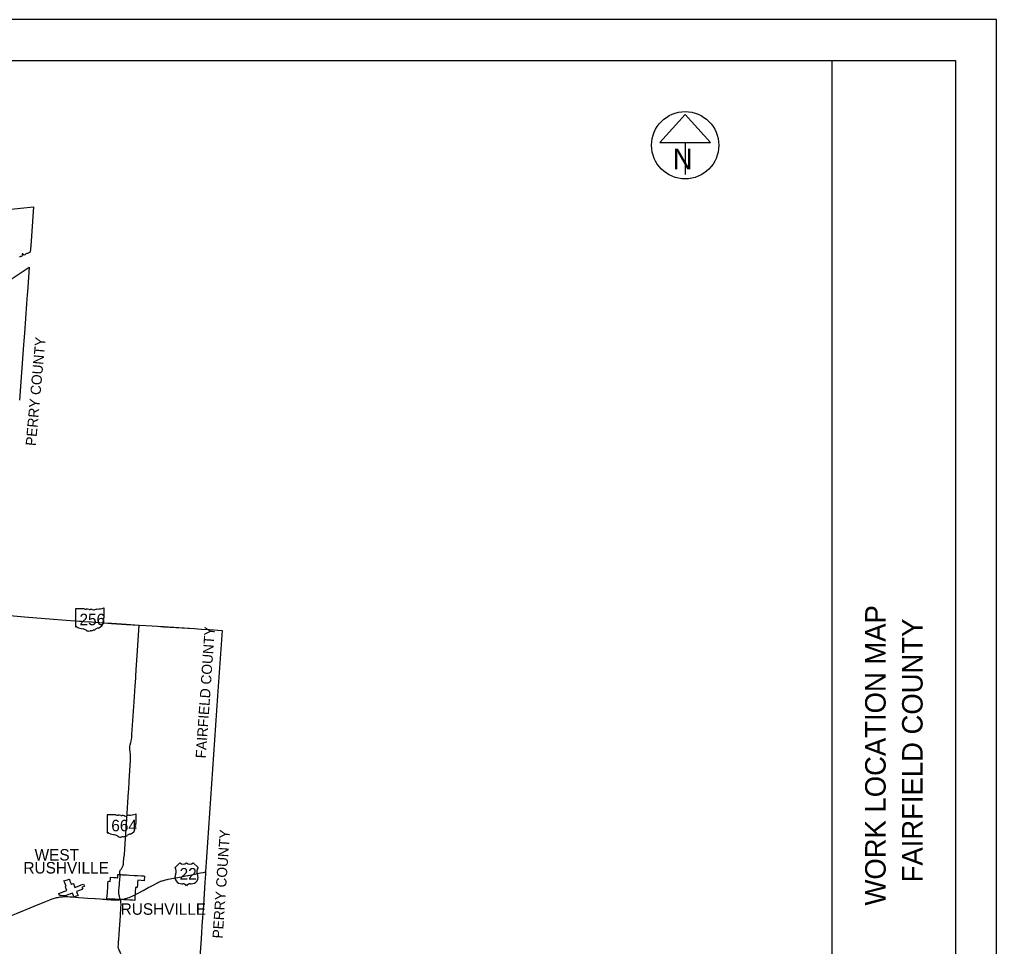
# Model space of a CAD drawing. Extents: x 1801177 to 2073177, y 78841 to 727183.
# Drawn here: x 1977949 to 2073177, y 636851 to 727183 of the extents above; entities that cross this region are included whole.
import ezdxf

# ---------------------------------------------------------------- set-up
doc = ezdxf.new("R2010")
doc.units = 0
for name, color, linetype in [('GM_X_Corporation', 7, 'Continuous'), ('GM_X_Corporation_Text', 7, 'Continuous'), ('GM_X_County', 7, 'Continuous'), ('GM_X_County_Text', 7, 'Continuous'), ('GM_X_State_Location', 7, 'Continuous'), ('GM_X_State_Route', 7, 'Continuous'), ('GM_X_State_Shield', 7, 'Continuous'), ('GM_X_US_Location', 7, 'Continuous'), ('GM_X_US_Route', 7, 'Continuous'), ('GM_X_US_Shield', 7, 'Continuous'), ('SH_Border', 7, 'Continuous'), ('SH_Cut_Line', 7, 'Continuous'), ('SH_Data', 7, 'Continuous'), ('SH_Masking', 7, 'Continuous'), ('SH_Text', 7, 'Continuous')]:
    doc.layers.add(name, color=color, linetype=linetype)

msp = doc.modelspace()

# ---------------------------------------------------------------- linework, layer by layer
at = {"layer": 'GM_X_Corporation'}
msp.add_lwpolyline([(1976528, 708641), (1978057, 708794), (1979311, 708937), (1979058, 705139), (1978993, 704509), (1978936, 704465), (1978868, 704437), (1978792, 704409), (1978716, 704390), (1978664, 704374), (1978590, 704338), (1978514, 704306), (1978456, 704250), (1978390, 704227), (1978330, 704273), (1978286, 704337), (1978220, 704359), (1978218, 704297), (1978234, 704225), (1978216, 704159), (1978167, 704107), (1978117, 704085), (1978052, 704076), (1978000, 704064), (1977932, 704064)], dxfattribs=at)
for points in [[(1987529, 643872), (1987620, 643866), (1987739, 643859), (1987841, 643852), (1987952, 643845), (1988387, 643819), (1988673, 643801), (1989115, 643774), (1989211, 643768), (1989240, 643767), (1989454, 643754), (1989826, 643733), (1990070, 643719), (1990101, 643717), (1990130, 643714), (1990129, 643694), (1990101, 643261), (1989795, 643280), (1989466, 643300), (1989454, 643095), (1989447, 642983), (1989441, 642872), (1989434, 642758), (1989430, 642696), (1989427, 642642), (1989425, 642608), (1989421, 642607), (1989419, 642607), (1989419, 642607), (1989415, 642607), (1989415, 642607), (1989412, 642606), (1989412, 642606), (1989412, 642606), (1989411, 642606), (1989409, 642606), (1989407, 642605), (1989405, 642605), (1989405, 642605), (1989404, 642605), (1989403, 642605), (1989402, 642605), (1989400, 642605), (1989399, 642604), (1989398, 642604), (1989396, 642604), (1989396, 642604), (1989395, 642604), (1989393, 642604), (1989391, 642604), (1989391, 642604), (1989390, 642603), (1989389, 642603), (1989389, 642603), (1989388, 642603), (1989385, 642603), (1989384, 642603), (1989382, 642603), (1989381, 642603), (1989378, 642602), (1989378, 642602), (1989375, 642602), (1989374, 642602), (1989373, 642602), (1989371, 642602), (1989370, 642602), (1989368, 642602), (1989367, 642602), (1989366, 642602), (1989364, 642602), (1989363, 642602), (1989360, 642602), (1989359, 642601), (1989357, 642601), (1989356, 642601), (1989353, 642601), (1989352, 642601), (1989350, 642601), (1989348, 642601), (1989346, 642601), (1989345, 642601), (1989343, 642601), (1989342, 642601), (1989341, 642601), (1989339, 642601), (1989337, 642601), (1989336, 642601), (1989336, 642601), (1989333, 642602), (1989332, 642602), (1989330, 642602), (1989329, 642602), (1989326, 642602), (1989326, 642602), (1989325, 642602), (1989322, 642602), (1989322, 642602), (1989321, 642602), (1989321, 642602), (1989319, 642602), (1989318, 642602), (1989315, 642602), (1989254, 642607), (1989228, 642155), (1989217, 641986), (1989202, 641756), (1989181, 641335), (1988961, 641349), (1988798, 641359), (1988696, 641367), (1988227, 641401), (1988101, 641409), (1987882, 641414), (1987467, 641441), (1987250, 641455), (1987137, 641463), (1986458, 641508), (1986470, 641574), (1986484, 641752), (1986518, 642168), (1986518, 642208), (1986542, 642581), (1986549, 642689), (1986553, 642745), (1986557, 642811), (1986563, 642898), (1986568, 642976), (1986569, 642986), (1986580, 643161), (1986582, 643205), (1986782, 643193), (1986803, 643488), (1986811, 643592), (1987141, 643573), (1987173, 643571), (1987366, 643559), (1987512, 643550), (1987515, 643550), (1987518, 643611), (1987523, 643695), (1987528, 643829)], [(1981777, 641999), (1982356, 642224), (1982567, 642306), (1982463, 642578), (1982437, 642644), (1982418, 642690), (1982507, 642725), (1982354, 643041), (1982282, 643232), (1982622, 643340), (1982798, 643396), (1982809, 643366), (1982821, 643338), (1982843, 643280), (1982866, 643219), (1982890, 643157), (1982897, 643140), (1982914, 643095), (1982937, 643034), (1982961, 642972), (1982976, 642907), (1983008, 642919), (1983014, 642922), (1983025, 642926), (1983030, 642928), (1983168, 642981), (1983199, 642993), (1983276, 642798), (1983351, 642610), (1983427, 642639), (1983495, 642666), (1983766, 642771), (1983893, 642820), (1983939, 642838), (1983948, 642841), (1984181, 642932), (1984212, 642855), (1984242, 642781), (1984242, 642781), (1984254, 642750), (1984272, 642705), (1984248, 642692), (1984091, 642631), (1984037, 642611), (1984103, 642441), (1984096, 642439), (1984042, 642418), (1983847, 642342), (1983844, 642341), (1983503, 642209), (1983575, 642024), (1983652, 641824), (1983502, 641763), (1983476, 641756), (1983384, 641720), (1983263, 641673), (1983252, 641669), (1983252, 641669), (1983250, 641674), (1983244, 641691), (1983229, 641730), (1983218, 641758), (1983203, 641795), (1983166, 641892), (1983131, 641982), (1983103, 642053), (1982905, 641977), (1982847, 641954), (1982718, 641904), (1982503, 641821), (1982446, 641796), (1982453, 641781), (1982435, 641782), (1982407, 641784), (1982298, 641792), (1982267, 641794), (1982172, 641800), (1981982, 641813), (1981934, 641816), (1981903, 641818), (1981844, 641822)]]:
    msp.add_lwpolyline(points, close=True, dxfattribs=at)
at = {"layer": 'GM_X_County'}
for points in [[(1976042, 701178), (1978895, 703062), (1978712, 700602), (1978706, 700391), (1978667, 699941), (1978642, 699484), (1978418, 696607), (1978363, 695865), (1978334, 695468), (1977935, 690100)], [(1977351, 669074), (1978441, 668981), (1979643, 668883), (1980046, 668846), (1981255, 668751), (1982076, 668690), (1983806, 668565), (1983991, 668552), (1984208, 668534), (1984949, 668481), (1986554, 668366), (1986914, 668342), (1988365, 668246), (1989608, 668172), (1990876, 668088), (1991394, 668058), (1991997, 668018), (1994999, 667826), (1995657, 667780), (1996458, 667729), (1997712, 667641), (1997257, 661263), (1996967, 656986), (1996091, 644115), (1996081, 643913), (1996050, 643471), (1996022, 643076), (1995867, 640886), (1995720, 638854), (1995677, 638161), (1995645, 637665), (1995639, 637582), (1995510, 635849)]]:
    msp.add_lwpolyline(points, dxfattribs=at)
at = {"layer": 'GM_X_State_Route'}
for points in [[(1976201, 669170), (1976410, 669152), (1976776, 669121), (1977352, 669071), (1978442, 668978), (1979644, 668880), (1980047, 668843), (1981257, 668749), (1982077, 668687), (1983807, 668562), (1983992, 668550), (1984209, 668532), (1984950, 668478), (1986556, 668363), (1986915, 668339), (1988366, 668243), (1989609, 668170)], [(1988904, 657448), (1988907, 657500), (1989124, 660690), (1989229, 662265), (1989276, 662985), (1989293, 663203), (1989332, 663813), (1989430, 665191), (1989609, 668170)], [(1989609, 668170), (1990877, 668085), (1991395, 668055), (1991998, 668015), (1995000, 667823), (1995658, 667777), (1996459, 667726), (1997714, 667638)], [(1988770, 655208), (1988778, 655382), (1988770, 655542), (1988754, 655640), (1988738, 655770), (1988726, 655859), (1988710, 656003), (1988700, 656123), (1988702, 656247), (1988716, 656367), (1988748, 656507), (1988802, 656734), (1988830, 656861), (1988864, 657043), (1988882, 657170), (1988895, 657312), (1988904, 657448)], [(1988128, 645454), (1988130, 645479), (1988169, 645787), (1988212, 646362), (1988281, 647364), (1988300, 647617), (1988358, 648470), (1988407, 649294), (1988580, 651954), (1988589, 652163), (1988634, 652934), (1988734, 654532), (1988762, 654948), (1988770, 655208)], [(1987727, 643889), (1987724, 643908), (1987718, 643964), (1987716, 644013), (1987716, 644062), (1987719, 644094), (1987724, 644126), (1987731, 644158), (1987741, 644189), (1987752, 644219), (1987773, 644263), (1987796, 644305), (1987872, 644431), (1987982, 644614), (1988023, 644685), (1988044, 644730), (1988056, 644761), (1988066, 644793), (1988072, 644825), (1988079, 644891), (1988091, 645038), (1988128, 645454)], [(1987667, 642704), (1987678, 642860), (1987692, 643036), (1987717, 643359), (1987729, 643471), (1987744, 643618), (1987747, 643668), (1987745, 643733), (1987743, 643772), (1987739, 643811), (1987730, 643870), (1987727, 643889)], [(1987775, 641412), (1987735, 641556), (1987679, 641762), (1987660, 641842), (1987650, 641900), (1987635, 641992), (1987628, 642123), (1987634, 642250), (1987667, 642704)], [(1987828, 640664), (1987840, 640878), (1987843, 640960), (1987838, 641091), (1987833, 641139), (1987810, 641268), (1987775, 641412)], [(1987847, 635993), (1987816, 636165), (1987802, 636203), (1987771, 636283), (1987722, 636383), (1987676, 636483), (1987627, 636588), (1987602, 636653), (1987586, 636728), (1987576, 636797), (1987593, 637050), (1987602, 637309), (1987607, 637412), (1987621, 637490), (1987663, 638083), (1987781, 639845), (1987828, 640664)]]:
    msp.add_lwpolyline(points, dxfattribs=at)
at = {"layer": 'GM_X_State_Shield'}
for p, q in [((1983388, 669738), (1983388, 668037)), ((1984237, 669767), (1983416, 669767)), ((1986190, 668920), (1986190, 669810)), ((1986190, 668920), (1986190, 668920)), ((1986500, 649659), (1986500, 647957)), ((1987348, 649688), (1986528, 649688)), ((1989302, 648840), (1989302, 649730)), ((1989301, 648840), (1989302, 648840))]:
    msp.add_line(p, q, dxfattribs=at)
for centre, major_axis, start_param, end_param in [((1983421, 669742), (32.5, 0), 1.712693, 3.28349), ((1984432, 669965), (315, 0), 4.042523, 4.731795), ((1984536, 668812), (1130, 0), 1.404758, 1.657858), ((1984793, 669751), (90.8, 0), 3.836095, 5.185415), ((1984926, 669554), (189, 0), 0.950623, 2.079405), ((1985170, 669824), (227, 0), 4.081561, 5.145723), ((1985571, 669248), (598, 0), 1.699011, 2.107814), ((1985192, 672087), (2971, 0), 4.814394, 5.042369), ((1986159, 669813), (31.2, 0), 6.141152, 7.989035), ((1985359, 668434), (743, 0), 5.101752, 6.440018), ((1986302, 668547), (211, 0), 2.387724, 3.262537), ((1986183, 668854), (48.3, 0), 1.883978, 3.671073), ((1985876, 668742), (290, 0), 5.934695, 6.695948), ((1986157, 668916), (33.4, 0), 5.05454, 6.418171), ((1983421, 668033), (32.7, 0), 3.00124, 4.508301), ((1983426, 668207), (250, 0), 4.665946, 4.897461), ((1983477, 667939), (90.1, 0), 0.519207, 1.627899), ((1984615, 669467), (2146, 0), 4.195997, 4.488961), ((1983975, 667273), (671, 0), 0.823519, 1.323587), ((1984701, 667930), (426, 0), 4.026481, 4.996735), ((1984947, 667342), (350, 0), 1.495662, 1.94098), ((1984978, 667803), (227, 0), 4.691044, 5.507374), ((1985184, 667638), (63.9, 0), 1.147584, 2.315152), ((1985156, 667872), (240, 0), 4.937069, 5.64225), ((1985672, 667559), (407, 0), 1.647645, 2.488434), ((1986532, 649662), (32.5, 0), 1.712693, 3.28349), ((1987543, 649885), (315, 0), 4.042523, 4.731795), ((1987648, 648733), (1130, 0), 1.404758, 1.657858), ((1987904, 649671), (90.8, 0), 3.836095, 5.185415), ((1988038, 649474), (189, 0), 0.950623, 2.079405), ((1988281, 649744), (227, 0), 4.081561, 5.145723), ((1988683, 649168), (598, 0), 1.699011, 2.107814), ((1988304, 652007), (2971, 0), 4.814394, 5.042369), ((1989271, 649734), (31.2, 0), 6.141152, 7.989035), ((1989413, 648468), (211, 0), 2.387724, 3.262537), ((1989294, 648775), (48.3, 0), 1.883978, 3.671073), ((1988987, 648662), (290, 0), 5.934695, 6.695948), ((1989268, 648837), (33.4, 0), 5.05454, 6.418171), ((1986532, 647954), (32.7, 0), 3.00124, 4.508301), ((1986537, 648128), (250, 0), 4.665946, 4.897461), ((1986588, 647859), (90.1, 0), 0.519207, 1.627899), ((1987726, 649388), (2146, 0), 4.195997, 4.488961), ((1987086, 647193), (671, 0), 0.823519, 1.323587), ((1987812, 647851), (426, 0), 4.026481, 4.996735), ((1988090, 647723), (227, 0), 4.691044, 5.507374), ((1988295, 647559), (63.9, 0), 1.147584, 2.315152), ((1988268, 647792), (240, 0), 4.937069, 5.64225), ((1988783, 647480), (407, 0), 1.647645, 2.488434), ((1988470, 648354), (743, 0), 5.101752, 6.440018), ((1988059, 647263), (350, 0), 1.495662, 1.94098)]:
    msp.add_ellipse(centre, major_axis=major_axis, ratio=0.8, start_param=start_param, end_param=end_param, dxfattribs=at)
at = {"layer": 'GM_X_US_Route'}
for points in [[(1992352, 643376), (1992441, 643396), (1992998, 643517), (1993393, 643581), (1994337, 643767), (1994412, 643782), (1994852, 643870), (1995591, 644015), (1995894, 644074), (1996092, 644112)], [(1990560, 642627), (1990652, 642678), (1991093, 642900), (1991326, 643021), (1991433, 643070), (1991643, 643166), (1991737, 643209), (1991806, 643236), (1991883, 643256), (1991975, 643283), (1992091, 643314), (1992190, 643340), (1992352, 643376)], [(1987775, 641412), (1987878, 641426), (1987988, 641445), (1988081, 641462), (1988194, 641487), (1988290, 641512), (1988385, 641539), (1988511, 641578), (1988620, 641616), (1988774, 641676), (1988865, 641715), (1989073, 641816), (1989216, 641894)], [(1989216, 641894), (1989438, 642015), (1989987, 642308), (1990560, 642627)], [(1976677, 639673), (1977007, 639814), (1977656, 640075), (1979389, 640789), (1980565, 641262), (1980898, 641392)], [(1980898, 641392), (1981144, 641487), (1981252, 641524), (1981457, 641584), (1981553, 641608), (1981682, 641635), (1981775, 641652), (1981801, 641656), (1981925, 641674), (1982039, 641687), (1982132, 641697), (1982263, 641705), (1982441, 641710), (1982521, 641710), (1982644, 641706), (1982865, 641692), (1983068, 641679), (1983737, 641632), (1984171, 641599)], [(1984171, 641599), (1984596, 641567), (1985282, 641519)], [(1985282, 641519), (1985318, 641517), (1985806, 641484)], [(1985806, 641484), (1986057, 641467), (1986311, 641446)], [(1986311, 641446), (1986414, 641438), (1986613, 641422), (1986873, 641403), (1987149, 641387), (1987262, 641383), (1987360, 641383), (1987474, 641386), (1987588, 641393), (1987701, 641403), (1987775, 641412)]]:
    msp.add_lwpolyline(points, dxfattribs=at)
at = {"layer": 'GM_X_US_Shield'}
for p, q in [((1993571, 645007), (1993104, 644540)), ((1995346, 644540), (1994879, 645007)), ((1993758, 642952), (1993851, 642952)), ((1994598, 642952), (1994692, 642952))]:
    msp.add_line(p, q, dxfattribs=at)
for centre, radius, start, end in [((1993898, 645340), 467, 225.573, 314.427), ((1994552, 645340), 467, 225.573, 314.427), ((1993751, 643606), 654, 154.83192, 270.63826), ((1992569, 644165), 654, 334.54712, 35.00093), ((1994699, 643606), 654, 269.36174, 25.16808), ((1995881, 644165), 654, 144.99907, 205.45288), ((1993851, 642485), 467, 36.8699, 90), ((1994598, 642485), 467, 90, 143.1301)]:
    msp.add_arc(centre, radius, start, end, dxfattribs=at)
at = {"layer": 'SH_Border'}
msp.add_line((2057177, 555183), (2057177, 723183), dxfattribs=at)
msp.add_lwpolyline([(1813177, 723183), (2069177, 723183), (2069177, 555183), (1813177, 555183)], close=True, dxfattribs=at)
at = {"layer": 'SH_Cut_Line'}
msp.add_lwpolyline([(1801177, 551183), (2073177, 551183), (2073177, 727183), (1801177, 727183)], close=True, dxfattribs=at)
at = {"layer": 'SH_Masking'}
msp.add_circle((2042831, 714932), 3280, dxfattribs=at)
at = {"layer": 'SH_Text'}
for p, q in [((2042831, 717922), (2040370, 715192)), ((2045291, 715192), (2042831, 717922)), ((2040370, 715192), (2045291, 715192)), ((2042831, 715192), (2042831, 712098))]:
    msp.add_line(p, q, dxfattribs=at)
msp.add_circle((2042831, 714932), 3280, dxfattribs=at)

# ---------------------------------------------------------------- texts
at = {"layer": 'GM_X_Corporation_Text'}
for s, p in [('WEST', (1979419, 645220)), ('RUSHVILLE', (1978330, 643960)), ('RUSHVILLE', (1987809, 639938))]:
    msp.add_text(s, height=1120, rotation=0.00001, dxfattribs=at).set_placement(p)
at = {"layer": 'GM_X_County_Text'}
for s, rotation, p in [('PERRY COUNTY', 84.79025, (1979533, 685599)), ('FAIRFIELD COUNTY', 86.01588, (1996106, 655157)), ('PERRY COUNTY', 86.07844, (1997747, 637600))]:
    msp.add_text(s, height=1000, rotation=rotation, dxfattribs=at).set_placement(p)
at = {"layer": 'GM_X_State_Location'}
msp.add_text('256', height=1, rotation=0.00001, dxfattribs=at).set_placement((1984576, 668289))
for s in ['s', 'r']:
    msp.add_text(s, height=1, dxfattribs=at).set_placement((1984929, 668362))
at = {"layer": 'GM_X_State_Shield'}
for s, p in [('256', (1983792, 668157)), ('664', (1986895, 648077))]:
    msp.add_text(s, height=1120.7, dxfattribs=at).set_placement(p)
at = {"layer": 'GM_X_US_Location'}
msp.add_text('22', height=1, rotation=0.00001, dxfattribs=at).set_placement((1994018, 643508))
for s in ['0', '/']:
    msp.add_text(s, height=1, dxfattribs=at).set_placement((1994225, 643715))
at = {"layer": 'GM_X_US_Shield'}
msp.add_text('22', height=1120.7, dxfattribs=at).set_placement((1993555, 643373))
at = {"layer": 'SH_Data'}
for s, p in [('WORK LOCATION MAP', (2062377, 640841)), ('FAIRFIELD COUNTY', (2065977, 643097))]:
    msp.add_text(s, height=2000, rotation=90, dxfattribs=at).set_placement(p)
at = {"layer": 'SH_Text'}
msp.add_text('N', height=2000, dxfattribs=at).set_placement((2041620, 712601))

doc.saveas('drawing.dxf')
